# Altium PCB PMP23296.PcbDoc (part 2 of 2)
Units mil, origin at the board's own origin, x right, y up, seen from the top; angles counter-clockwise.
Board outline 4000 x 1600 mil, 2 copper layers (Top Layer, Bottom Layer), stack 62 mil thick; 43 components, 23 nets, 108 pads, 16 vias.
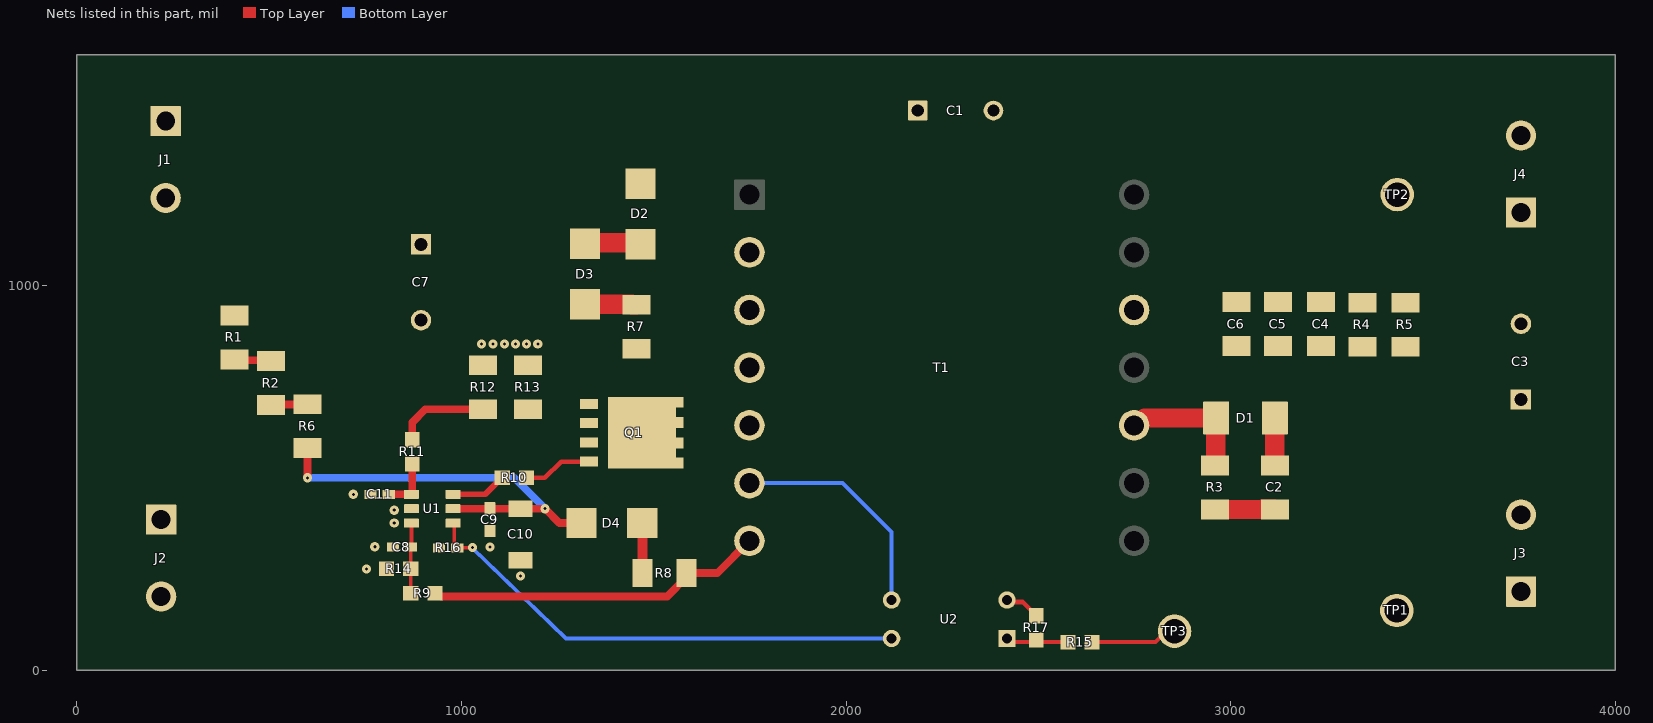
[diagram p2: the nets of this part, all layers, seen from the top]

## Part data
C1: library part CMP-0095357-1, "Cap Ceramic Single Suppression X1/Y2 0.0022uF 250VAC E 20% (8 X 5mm) Radial Disc 5mm 125C Ammo", Digikey Part Number=490-9555-1-ND, Manufacturer=Murata, Mouser Part Number=81-DE2E3KY222MN2AM1F, Operating Temperature Range="-40°C to +125°C", TempCo=+20/-55%, Temperature Characteristic=E, Tolerance_%=20%, ValueDisplayed=2200pF, Voltage Ac Rating X=250V
C2: library part CMP-0008884-2, "CAP, CERM, 100 pF, 630 V, +/- 5%, C0G/NP0, 1206", Cap_Case=1206, Manufacturer=MuRata, Supplier Part Number 1=490-5273-1-ND, TempCo=C0G/NP0, Tolerance_%=5%, Value1=Unknown, Value2=630V, ValueDisplayed=100pF
C3: library part CMP-0010235-2, "CAP, AL, 22 uF, 200 V, +/- 20%, TH", Cap_Case=10x20mm, Manufacturer=Nichicon, Supplier Part Number 1=493-4765-1-ND, Tolerance_%=20%, Value1=Unknown, Value2=200V, ValueDisplayed=22uF
C4 C5 C6: library part CMP-0008585-2, "CAP, CERM, 0.1 uF, 200 V, +/- 10%, X7R, 1206", Cap_Case=1206, Manufacturer=Kemet, Supplier Part Number 1=399-8139-1-ND, TempCo=X7R, Tolerance_%=10%, Value1=Unknown, Value2=200V, ValueDisplayed=0.1uF
C7: library part CMP-0064890-1, "CAP, AL, 22 uF, 200 V, +/- 20%, TH", Cap_Case=10x20mm, Manufacturer=Nichicon, Supplier Part Number 1=493-11959-1-ND, Tolerance_%=20%, Value1=Unknown, Value2=200V, ValueDisplayed=22uF
C8 C11: library part CMP-0064914-2, "CAP, CERM, 10 pF, 10 V,+/- 2.5%, C0G/NP0, 0402", Cap_Case=0402, Manufacturer=Kemet, Supplier Part Number 1=399-8939-1-ND, TempCo=C0G/NP0, Tolerance_%=2.5%, Value1=Unknown, Value2=10V, ValueDisplayed=10pF
C9: library part CMP-0094511-1, "0.1 µF ±5% 50V Ceramic Capacitor X7R 0603 (1608 Metric)", Digikey Part Number=478-7426-1-ND, Manufacturer="KYOCERA AVX", Mouser Part Number=581-06035C104J4Z2A, Operating Temperature Range=to, TempCo=15%, Temperature Characteristic=X7R, Tolerance_%=5%, ValueDisplayed=0.1uF
C10: library part CMP-0008660-2, "CAP, CERM, 2.2 uF, 50 V, +/- 10%, X5R, 1206", Cap_Case=1206_180, Manufacturer=TDK, Supplier Part Number 1=445-14690-1-ND, TempCo=X5R, Tolerance_%=10%, Value1="0.005887 ohm", Value2=50V, ValueDisplayed=2.2uF
D1: library part CMP-0096282-1, "Diode Standard 600 V 2A Surface Mount DO-214AA (SMB)", Digikey Part Number=MURS260-E3/5BTGICT-ND, Forward Current=2A, Manufacturer=Vishay, Max Surge Forward Current=35A, Mouser Part Number=625-MURS260-E3/5BT, Operating Temperature Range="-65°C to +175°C", Peak Reverse Current=5uA
D2: library part CMP-0084980-1, "Diode, TVS, Uni, 120 V, 193 Vc, 400 W, 2.1 A, SMA", Manufacturer=Littelfuse, Value1=193V
D3: library part CMP-0076882-2, "Diode, Ultrafast, 1000 V, 1 A, SMA", Manufacturer="Diodes Inc.", Value1=1A, Value2=1.7V
D4: library part CMP-0081057-2, "Diode, Schottky, 100 V, 4 A, AEC-Q101, SMA", Manufacturer="ON Semiconductor", Value1=4A, Value2=0.68V
J1 J2 J3 J4: library part CMP-0074910-1, "Terminal Block, 5.08 mm, 2x1, Brass, TH", Color=Blue, Current_A=15A, Manufacturer="On-Shore Technology", Supplier Part Number 1=ED1609-ND, Voltage_V=300V
Q1: library part CMP-0000907-1, "MOSFET, N-CH, 300 V, 16 A, PG-TDSON-8", Alternate Manufacturer=None, Manufacturer="Infineon Technologies"
R1 R2 R6: library part CMP-0018313-2, "RES, 470 k, 1%, 0.25 W, 1206", Manufacturer="Yageo America", Power_W=250mW, Supplier Part Number 1=311-470KFRCT-ND, TempCo="100 ppm/C", Tolerance_%=1%, Value2=0.25W, Value_Code=470k
R3: library part CMP-0018748-3, "RES, 0, 5%, 0.25 W, AEC-Q200 Grade 0, 1206", Manufacturer=Panasonic, Power_W=250mW, Supplier Part Number 1=P0.0ECT-ND, TempCo="600 ppm/C", Tolerance_%=5%, Value2=0.25W, Value_Code=0000, ValueDisplayed=0
R4 R5: library part CMP-0017836-2, "RES, 100 k, 1%, 0.25 W, 1206", Manufacturer="Yageo America", Power_W=250mW, Supplier Part Number 1=311-100KFRCT-ND, TempCo="100 ppm/C", Tolerance_%=1%, Value2=0.25W, Value_Code=100k
R7: library part CMP-0018594-3, "RES, 15, 5%, 0.25 W, AEC-Q200 Grade 0, 1206", Manufacturer=Vishay-Dale, Power_W=250mW, Supplier Part Number 1=541-15ECT-ND, TempCo="200 ppm/C", Tolerance_%=5%, Value2=0.25W, Value_Code=15R0, ValueDisplayed=15
R8: library part CMP-0018350-2, "RES, 4.70, 1%, 0.25 W, 1206", Manufacturer="Yageo America", Power_W=250mW, Supplier Part Number 1=311-4.70FRCT-ND, TempCo="200 ppm/C", Tolerance_%=1%, Value2=0.25W, Value_Code=4R70, ValueDisplayed=4.70
R9: library part CMP-0024509-1, "RES, 87.6 k, 0.1%, 0.1 W, 0603", Manufacturer="Yageo America", Power_W=100mW, TempCo="25 ppm/C", Tolerance_%=0.1%, Value2=0.1W, Value_Code=87k6, ValueDisplayed=87.6k
R10: library part CMP-0025874-2, "RES, 0, 5%, 0.1 W, 0603", Manufacturer=Panasonic, Power_W=100mW, Supplier Part Number 1=P0.0GCT-ND, TempCo="600 ppm/C", Tolerance_%=5%, Value2=0.1W, Value_Code=0000, ValueDisplayed=0
R11: library part CMP-0022118-2, "RES, 1.24 k, 1%, 0.1 W, 0603", Manufacturer=Vishay-Dale, Power_W=100mW, Supplier Part Number 1=541-1.24KHCT-ND, TempCo="100 ppm/C", Tolerance_%=1%, Value2=0.1W, Value_Code=1k24, ValueDisplayed=1.24k
R12 R13: library part CMP-0017791-3, "RES, 0.47, 1%, 0.25 W, AEC-Q200 Grade 0, 1206", Manufacturer=Panasonic, Power_W=250mW, Supplier Part Number 1=P.47RCT-ND, TempCo="250 ppm/C", Tolerance_%=1%, Value2=0.25W, Value_Code=R470, ValueDisplayed=0.47
R14: library part CMP-0022261-1, "RES, 28.7 k, 1%, 0.1 W, 0603", Manufacturer=Vishay-Dale, Power_W=100mW, Supplier Part Number 1=541-28.7KHCT-ND, TempCo="100 ppm/C", Tolerance_%=1%, Value2=0.1W, Value_Code=28k7, ValueDisplayed=28.7k
R15 R17: library part CMP-0080488-1, "RES, 10.0 k, 1%, 0.1 W, 0603", Manufacturer="TT Electronics/IRC", Power_W=100mW, TempCo="100 ppm/C", Tolerance_%=1%, Value2=0.1W, Value_Code=10k0, ValueDisplayed=10.0k
R16: library part CMP-0026721-1, "RES, 100 k, 1%, 0.0625 W, 0402", Manufacturer="Yageo America", Power_W=62.5mW, Supplier Part Number 1=311-100KLRCT-ND, TempCo="100 ppm/C", Tolerance_%=1%, Value2=0.0625W, Value_Code=100k
T1: library part CMP-0096302-1, "TRANSFORMER", Frequency_Fixed=25-85kHz, Manufacturer="Wurth Electronics", Operating Temperature Range="-40°C to +125°C", Voltage_Isolation_Vrms=2.85kV
TP1: library part CMP-0055147-2, "Test Point, Multipurpose, Red, TH", Color=Red, Manufacturer="Keystone Electronics", Supplier Part Number 1=36-5010-ND
TP2: library part CMP-0055148-2, "Test Point, Multipurpose, Black, TH", Color=Black, Manufacturer="Keystone Electronics", Supplier Part Number 1=36-5011-ND
TP3: library part CMP-0055150-2, "Test Point, Multipurpose, Orange, TH", Color=Orange, Manufacturer="Keystone Electronics", Supplier Part Number 1=36-5013-ND
U1: library part CMP-0074087-1, "Off-Line Constant-Voltage Constant-Current Flyback Controller With Primary-Side Regulation (PSR), DBV0006A (SOT-23-6)", Alternate Manufacturer="Texas Instruments", Alternate PartNumber=UCC28704DBVT-1
U2: library part CMP-0083653-1, "Optocoupler, 5.3 kV, 100-200% CTR, SMT", Manufacturer=Vishay-Semiconductor, Supplier Part Number 1=VO618A-3-ND, Voltage_Isolation_Vrms=5.3kV

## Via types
v1: diameter 24, hole 8, Top Layer to Bottom Layer, tented both sides, 16 vias

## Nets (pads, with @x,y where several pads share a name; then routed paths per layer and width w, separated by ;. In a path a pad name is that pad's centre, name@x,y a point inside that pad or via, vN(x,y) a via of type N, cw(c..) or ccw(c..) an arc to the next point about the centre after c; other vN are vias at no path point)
BGND: C1.1 C7.2 C8.2 C9.1 C10.2 C11.2 J2.1 J2.2 R12.1 R13.1 R14.1 R16.1 T1.6 U1.5 U2.3 | length 599
  Bottom Layer w10: T1.6@1749.01,486.35 1991.22,486.35 2118.7,358.87 U2.3@2118.7,182.34
  other v1: 1153.72,245 752.95,263.25 1074.33,320 775,320.92 825.38,382.37 825.38,415.93 719.04,457.17 1052.35,847.98 1081.88,847.98 1112.22,847.98 1140.85,847.98 1169.16,847.98 1198.84,847.98
NetC2_1: C2.1 C3.1 C4.1 C5.1 C6.1 D1.1 J3.1 J3.2 R4.2 R5.2 TP1.1 | length 123.5
  Top Layer w50: C2.1@3115.03,532.09 D1.1@3115.03,655.56
NetC2_2: C2.2 R3.2 | length 174.9
  Top Layer w50: R3.2@2973.78,417.91 C2.2@3115.03,417.91 3114.44,418.5 C2.2@3081.65,418.5
NetC7_1: C7.1 D2.2 J1.1 J1.2 R1.2 T1.2
NetC8_1: C8.1 R9.1 R14.2 U1.6 | length 206.3
  Top Layer w10: R9.1@857.51,210.81 R9.1@868.32,200 868.32,263.04 R14.2@868.53,263.25 868.53,319.37 C8.1@869.16,320 870.08,320.92 U1.6@870.08,382.37 U1.6@862.2,382.37
NetC11_1: C11.1 R11.1 U1.4 | length 138.9
  Top Layer w20: C11.1@811.02,457.17 U1.4@870.08,457.17 870.23,457.17 872.04,458.98 R11.1@872.04,536.12
NetD1_2: D1.2 R3.1 T1.10 | length 355.7
  Top Layer w50: T1.10@2749.01,636.35 2757,636.35 2776.21,655.56 2953.72,655.56 2960,649.27 D1.2@2960,640.05 ; R3.1@2960,532.09 2960.65,532.09 2961.24,532.68 2961.24,654.31 D1.2@2962.49,655.56
NetD2_1: D2.1 D3.1 | length 147.3
  Top Layer w50: D3.1@1321.48,1115.32 1325.39,1111.41 1461.64,1111.41 D2.1@1465.55,1107.5
NetD3_2: D3.2 R7.2 | length 134.2
  Top Layer w50: D3.2@1321.48,951.26 1442.68,951.26 1443.61,950.32 1454.44,950.32 R7.2@1455.03,949.73
NetD4_2: D4.2 R8.1 | length 130.4
  Top Layer w25: D4.2@1469.93,382.37 1470.97,381.33 R8.1@1470.97,252.42
NetQ1_1: Q1.1 Q1.2 Q1.3 R11.2 R12.2 R13.2 | length 243.4
  Top Layer w20: R11.2@872.04,599.11 872.04,643.87 906.49,678.32 R12.2@1056.41,678.32
NetQ1_4: Q1.4 R10.2 | length 180
  Top Layer w12: R10.2@1169.16,500.13 1217.19,500.13 1259.35,542.29 Q1.4@1331.69,542.29
NetQ1_5: Q1.5 Q1.6 Q1.7 Q1.8 Q1.9 R7.1 T1.5 | length 47.4
  Top Layer w50: Q1.9@1455.03,631.75 Q1.9@1469.49,617.29 Q1.9@1488.54,636.35
NetR1_1: R1.1 R2.2 | length 101.8
  Top Layer w10: R2.2@505,803.61 R2.2@508.56,807.17
  Top Layer w20: R1.1@410,807.91 412.15,805.76 502.85,805.76 R2.2@505,803.61
NetR2_1: R2.1 R6.2 | length 95.9
  Top Layer w20: R2.1@505,689.44 506.13,690.57 598.87,690.57 R6.2@600,691.7
NetR8_2: R8.2 R9.2 T1.7 | length 867.3
  Top Layer w20: R9.2@948.1,191.47 1535.01,191.47 1585.14,241.59 R8.2@1585.14,252.42 1665.09,252.42 T1.7@1749.01,336.35
NetR10_1: R10.1 U1.3 | length 145.6
  Top Layer w10: R10.1@1105.18,500.13 R10.1@1106.16,500.13
  Top Layer w15: U1.3@978.35,457.17 1062.23,457.17 R10.1@1105.18,500.13
NetR15_1: R15.1 R17.2 U2.1 | length 162
  Top Layer w10: U2.1@2418.7,82.34 2428.29,72.75 R15.1@2576.77,72.75
NetT1_3: T1.3 T1.4
PGND: C1.2 C3.2 C4.2 C5.2 C6.2 J4.1 J4.2 R4.1 R5.1 R17.1 T1.12 TP2.1 U2.2 | length 93.8
  Top Layer w12: U2.2@2418.7,182.34 2423.88,177.16 2459.34,177.16 2481.31,155.18 2482.3,155.18 2495,142.48 R17.1@2495,141.5
Shutdown_PM: R15.2 TP3.1 | length 226.4
  Top Layer w10: R15.2@2639.76,72.75 2804.95,72.75 2833.49,101.3 TP3.1@2854.33,101.3
SU: R16.2 U1.1 U2.4 | length 1295.8
  Top Layer w10: U1.1@978.35,382.37 981.3,379.42 981.3,324.59 988.11,317.78 R16.2@989.38,317.78 990.02,318.42 1028.43,318.42 v1(1029.07,319.06)
  Bottom Layer w10: v1@1028.03,317.78 1272.08,82.34 U2.4@2118.7,82.34
VDD: C9.2 C10.1 D4.1 R6.1 U1.2 | length 1109
  Top Layer w10: R6.1@600,577.53 R6.1@605.67,571.86 ; D4.1@1312.45,382.37 D4.1@1324.39,370.43
  Top Layer w20: v1(600,500.13) R6.1@600,577.53 ; U1.2@978.35,419.77 1073.11,419.77 C9.2@1074.33,420.99 ; C9.2@1070.3,415.93 1074.14,419.77 C10.1@1153.72,419.77 v1(1217.71,419.77) 1255.11,382.37 D4.1@1312.45,382.37
  Bottom Layer w20: v1(600,500.13) 1137.36,500.13 v1(1217.71,419.77)
pads on no net: T1.1 T1.8 T1.9 T1.11 T1.13 T1.14

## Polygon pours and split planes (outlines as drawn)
NetQ1_5 on Top Layer "TOP_LAYER_NETQ1_5_P021" (solid, remove dead copper, pour order 21): 1371.82,512.96 1373.94,510.84 1602.08,510.84 1665.66,574.42 1815.94,574.42 1815.94,688.75 1656.05,688.75 1590.56,754.24 1531.1,754.24 1501.29,784.05 1501.29,869.48 1408.77,869.48 1407.39,868.1 1407.39,782.1 1371.82,746.53
NetC2_1 on Top Layer "TOP_LAYER_NETC2_1_P024" (solid, remove dead copper, pour order 24): 2945.92,875.09 2945.92,746.43 2949.49,750 3065,750 3065,605 3175,605 3175,0 4000,0 4000,875
BGND on Top Layer "TOP_LAYER_BGND_P022" (solid, remove dead copper, pour order 22): 20.85,1010 20.85,85 645,85 790,230 1815.94,230 1815.94,1001.44 1807.39,1010
NetQ1_1 on Top Layer "TOP_LAYER_NETQ1_1_P020" (solid, remove dead copper, pour order 20): 1371.36,735.4 1370.91,734.95 1370.91,572.43 1050.49,572.43 988.31,634.62 990.15,636.46 990.15,735.4
PGND on Top Layer "TOP_LAYER_PGND_P014" (solid, pour order 14): 2680,875 4000,875 4000,1574.51 2680,1574.51
NetT1_3 on Top Layer "TOP_LAYER_NETT1_3_P000" (solid, pour order 0): 1677.3,735.4 1815.94,735.4 1815.94,982.77 1677.3,982.77
NetC7_1 on Top Layer "TOP_LAYER_NETC7_1_P012" (solid, pour order 12): 24.61,1563.91 24.61,895 527.71,895 576.16,943.45 1231.16,943.45 1231.16,1186.24 1240.05,1195.13 1542.32,1195.13 1542.32,1040.81 1581.69,1001.44 1811.67,1001.44 1811.67,1563.91
BGND on Bottom Layer "BOTTOM_LAYER_BGND_P023" (solid, remove dead copper, pour order 23): 25.49,263.25 25.49,85 700.54,85 878.79,263.25
PGND on Bottom Layer "BOTTOM_LAYER_PGND_P013" (solid, pour order 13): 2335,1600 2335,0 4000,0 4000,1600
BGND on Bottom Layer "BOTTOM_LAYER_BGND_P005" (solid, pour order 5): 0,1600 0,230 2215,230 2215,1594.49 5.51,1594.49
no net on M2 Board Dimensions (solid): 2221.46,1600 2224.41,1597.05 2224.41,0

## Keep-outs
Keep-Out Layer:
  text ".Layer_Name" at 577,-858.49 h60

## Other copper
Top Layer:
  text ".Layer_Name" at 577,-858.49 h60
Bottom Layer:
  pour cut-out: 845.54,394.71 903.66,394.71 903.66,228.54 845.54,228.54
  text ".Layer_Name" at 577,-858.49 h60

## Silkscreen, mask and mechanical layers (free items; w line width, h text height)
Top Overlay:
  lines w10: 990.76,223.88 990.76,290.51
  text "Vin" at 521.5,1316.32 h60 r90
  text "B_GND" at 511.5,210.26 h60 r90
  text ".Layer_Name" at 577,-858.49 h60
Bottom Overlay:
  text ".Layer_Name" at 577,-858.49 h60
Top Paste:
  text ".Layer_Name" at 577,-858.49 h60
Bottom Paste:
  text ".Layer_Name" at 577,-858.49 h60
Top Solder:
  text ".Layer_Name" at 577,-858.49 h60
  text ".Layer_Name" at 577,-858.49 h60
Bottom Solder:
  text ".Layer_Name" at 577,-858.49 h60
Drill Guide:
  text ".Layer_Name" at 577,-858.49 h60
M1 Board Outline:
  the board outline again, w10
  text ".Layer_Name" at 577,-858.49 h60
M2 Board Dimensions:
  rectangle: 0,-275 125,-150
  rectangle: 125,-400 500,-275
  lines w7: 0,-275 1000,-275 ; 125,-400 125,-150 ; 250,-400 250,-150 ; 500,-400 500,-150 ; 750,-400 750,-150 ; 0,-400 1000,-400 1000,-150 0,-150 0,-400
  text ".Layer_Name" at 577,-858.49 h60
M3 3D STEP Top:
  text ".Layer_Name" at 577,-858.49 h60
M4 3D STEP Bottom:
  text ".Layer_Name" at 577,-858.49 h60
M5 Assembly Top:
  lines w10: -292,-930.17 6308,-930.17 ; -292,-726.83 6310,-726.83 ; -292,-523.5 -292,-1133.5 3713,-1133.5 6310,-1133.5 6310,-523.5 -291.5,-523.5 -291.5,-1133.5 1284,-1133.5 ; 2173,-1133.5 2173,-523.5 ; 3440,-726.83 3440,-523.5 ; 4280,-726.83 4280,-523.5 ; 4902,-1140 4902,-937.17
  text "COMPONENTS MARKED 'DNP' SHOULD NOT BE POPULATED." at 1153.5,-318.5 h60
  text "ASSEMBLY VARIANT:" at 1153,-434 h60
  text ".VariantName" at 2189,-434 h60
  text "PCB VIEWED FROM TOP SIDE" at -228.5,-655.67 h60
  text "BOARD #:" at 2248,-655.67 h60
  text ".PRJ_Number" at 2793.5,-655.67 h60
  text "REV:" at 3638,-655.67 h60
  text ".PCB_Rev" at 3929.5,-655.67 h60
  text "SVN REV:" at 4476,-655.67 h60
  text ".VersionControl_RevNumber" at 4982,-655.67 h60
  text "TID #:" at 2248,-859 h60
  text ".TID" at 2793.5,-859 h60
  text "PLOT NAME =" at -228.5,-1064.34 h60
  text ".plot_File_Name" at 577,-1064.34 h60
  text "GENERATED    :" at 2250,-1064.34 h60
  text ".Print_Date" at 3119.5,-1064.34 h60
  text ".Print_Time" at 3848.5,-1064.34 h60
  text "TEXAS INSTRUMENTS" at 5113,-1064.34 h60
M6 Assembly Bottom:
  lines w10: -292.5,-727.33 6309.5,-727.33 ; -290.5,-930.67 6309.5,-930.67 ; 1115.5,-1140.5 1115.5,-937.67 ; 1737.5,-727.33 1737.5,-524 ; 2577.5,-727.33 2577.5,-524 ; 3844.5,-1134 3844.5,-524 ; 4733.5,-1134 6309,-1134 6309,-524 -292.5,-524 -292.5,-1134 2304.5,-1134 6309.5,-1134 6309.5,-524
  text "COMPONENTS MARKED 'DNP' SHOULD NOT BE POPULATED." at 6102,-318 h60
  text ".VariantName" at 5058,-434 h60
  text "ASSEMBLY VARIANT:" at 6097,-434 h60
  text ".VersionControl_RevNumber" at 1035.5,-656.17 h60
  text "SVN REV:" at 1541.5,-656.17 h60
  text ".PCB_Rev" at 2088,-656.17 h60
  text "REV:" at 2379.5,-656.17 h60
  text ".PRJ_Number" at 3224,-656.17 h60
  text "BOARD #:" at 3769.5,-656.17 h60
  text "PCB VIEWED FROM BOTTOM SIDE" at 6246,-656.17 h60
  text ".TID" at 3224,-859.5 h60
  text "TID #:" at 3769.5,-859.5 h60
  text "TEXAS INSTRUMENTS" at 904.5,-1064.84 h60
  text ".Print_Time" at 2169,-1064.84 h60
  text ".Print_Date" at 2898,-1064.84 h60
  text "GENERATED    :" at 3767.5,-1064.84 h60
  text ".plot_File_Name" at 5440.5,-1064.84 h60
  text "PLOT NAME =" at 6246,-1064.84 h60
M9 Title Sheet:
  drawing of 57 lines, arcs and shapes, not listed
  text "1" at 739.84,8036.5 h70
  text "2" at 3235.5,8036.5 h70
  text "3" at 5724.84,8036.5 h70
  text "4" at 8231.51,8036.5 h70
  text "5" at 10730.5,8036.5 h70
  text "6" at 13235.5,8036.5 h70
  text "A" at -416.5,6893.5 h70
  text "A" at 14383.5,6893.5 h70
  text "B" at -416.5,4513.5 h70
  text "B" at 14383.5,4513.5 h70
  text "C" at -416.5,2138.5 h70
  text "C" at 14383.5,2138.5 h70
  text "PROJECT TITLE:" at 11343.5,277.5 h45
  text ".PRJ_Title" at 11393.5,144.17 h70
  text "DESIGNED FOR:" at 11343.5,-23.5 h45
  text ".PRJ_Customer" at 11393.5,-163.5 h70
  text "D" at -416.5,-231.5 h70
  text "D" at 14383.5,-231.5 h70
  text "FILE NAME:" at 11343.5,-323.5 h45
  text ".PCB_File_Name_No_Path" at 11393.5,-443.5 h70
  text "Texas Instruments (TI) and/or its licensors do not warrant the accuracy or completeness of this specification" at 6374,-605.34 h45
  text "ENGINEER:" at 11343.5,-613.5 h45
  text "LAYOUT BY:" at 12848.5,-613.5 h45
  text "or any information contained therein. TI and/or its licensors do not warrant that this design will meet" at 6329.01,-718 h45
  text ".PRJ_Engineer" at 11393.5,-768.49 h70
  text ".PCB_Layout" at 12899,-768.49 h70
  text "the specifications, will be suitable for your application or fit for any particular purpose, or will operate in" at 6329.01,-830.67 h45
  text ".Layer_Name" at 577,-858.49 h60
  text "ALTIUM DESIGNER VERSION:" at 12848.5,-923.5 h45
  text "an implementation. TI and/or its licensors do not warrant that the design is production worthy. You should" at 6329.01,-943.33 h45
  text "completely validate and test your design implementation to confirm the system functionality for your application." at 6374,-1056 h45
  text ".print_Scale" at 11393.5,-1056.83 h70
  text ".Application_BuildNumber" at 12899,-1056.83 h70
  text "1" at 739.84,-1263.5 h70
  text "2" at 3235.5,-1263.5 h70
  text "3" at 5724.84,-1263.5 h70
  text "4" at 8231.51,-1263.5 h70
  text "5" at 10730.5,-1263.5 h70
  text "6" at 13235.5,-1263.5 h70
M10 Fab Notes:
  drawing of 189 lines, arcs and shapes, not listed
  text "DESIGN INFORMATION" at 12382.02,6356.17 h60
  text "MIN. TRACK WIDTH:" at 11737.46,6224.05 h60
  text "8" at 12833.7,6224.05 h60
  text "MIL" at 12988.46,6224.05 h60
  text "7.874" at 12667.32,6102.36 h60
  text "MIN. CLEARANCE:" at 11737.46,6099.92 h60
  text "MIL" at 12988.46,6099.92 h60
  text "MIN. VIA PAD SIZE:" at 11737.46,5975.8 h60
  text "24" at 12803.71,5975.8 h60
  text "MIL" at 12988.46,5975.8 h60
  text "0.05mm (2MIL)" at 12432.46,5845.9 h60
  text "MINIMUM ANNULAR RING" at 11408.23,5837.67 h60
  text "EXTERNAL" at 13140.46,5837.67 h60
  text "PER" at 11608.23,5727.55 h60
  text "IPC-D-275 CLASS 2 LEVEL C" at 11828.23,5727.54 h60
  text "MIL, HOLES" at 13316.46,5627.07 h60
  text "+/-" at 12924,5618.48 h60
  text "+/-" at 13778,5618.48 h60
  text "REGISTRATION TOLERANCES:" at 11408.23,5617.42 h60
  text "METAL" at 12608,5617.42 h60
  text "5" at 13184.2,5617.42 h60
  text "3" at 14017.2,5617.42 h60
  text "MIL" at 14133.46,5617.42 h60
  text "HOLE SIZE TOLERANCE (UNLESS OTHERWISE SPECIFIED):" at 11408.23,5519.1 h60
  text "+/-" at 13778,5516.23 h60
  text "3" at 14017.2,5515.17 h60
  text "MIL" at 14133.46,5515.17 h60
  text "MATERIAL:" at 11333.46,5377.52 h60
  text "FR-4 High Tg" at 12319.9,5249 h60
  text "X" at 12175.46,5241.01 h60
  text "FR-408" at 11754.46,5236.49 h60
  text "OTHER" at 13242.46,5236.49 h60
  text "62 MIL (1.6mm) +/-10%" at 12074.56,5093.46 h60
  text "X" at 11954.46,5091.01 h60
  text "THICKNESS:" at 11408.23,5085.24 h60
  text "OTHER" at 13359.46,5085.24 h60
  text "TOLERANCE:" at 11408.23,4946.92 h60
  text "X" at 12256.46,4946.92 h60
  text "ANSI IPC-6012 TYPE 3 CLASS 2" at 12434.48,4946.92 h60
  text "OTHER +/-" at 12434.46,4802.73 h60
  text "BOW & TWIST:" at 11408.23,4657.54 h60
  text "X" at 12256.46,4657.54 h60
  text "ANSI IPC-6012 TYPE 3 CLASS 2" at 12434.48,4657.54 h60
  text "OTHER +/-" at 12434.46,4510.85 h60
  text "DRILLING:" at 11333.46,4380.23 h60
  text "NC_DRILL FILES" at 13094.46,4275.04 h60
  text "REFERENCE:" at 11408.23,4271.1 h60
  text "X" at 12065.46,4271.01 h60
  text "AS SHOWN" at 12243.46,4271.1 h60
  text "X" at 12966.46,4271.1 h60
  text "OTHER" at 13392.46,4128.85 h60
  text "PTH COPPER THICKNESS:" at 11407.91,4125.32 h60
  text "X" at 12547.14,4125.32 h60
  text "20-30 um" at 12675.14,4125.32 h60
  text "BOARD FINISH:" at 11333.46,3977.73 h60
  text "SILKSCREEN:" at 11488.68,3867.6 h60
  text "X" at 12446.46,3867.6 h60
  text "TOP" at 12563.46,3867.6 h60
  text "X" at 12956.46,3867.6 h60
  text "BOTTOM" at 13074.46,3867.6 h60
  text "SILKSCREEN COLOR:" at 11488.68,3712.41 h60
  text "X" at 12445.46,3712.41 h60
  text "WHITE" at 12563.46,3712.41 h60
  text "OTHER" at 13074.46,3712.41 h60
  text "X" at 12576.46,3568.96 h60
  text "GREEN" at 12694.46,3568.96 h60
  text "OTHER" at 13312.46,3568.96 h60
  text "SOLDER RESIST COLOR:" at 11488.68,3562.1 h60
  text "X" at 12576.46,3414.71 h60
  text "MATTE" at 12694.46,3414.71 h60
  text "SEMI-GLOSS" at 13312,3414.07 h60
  text "IMMERSION GOLD (ENIG)" at 12394.46,3241.94 h60
  text "ENEPIG" at 13732,3234.72 h60
  text "SURFACE FINISH:" at 11333.46,3233.72 h60
  text "X" at 12216.46,3233.72 h60
  text "IMM. TIN/SILVER OR EQUIV" at 11663,3096.4 h60
  text "OTHER" at 13094.46,3092.47 h60
  text "ARRAY/PANEL:" at 11333.46,2937.09 h60
  text "CUT AND TRIM PER M1 BOARD OUTLINE" at 12394.46,2928.87 h60
  text "N.C. ROUTE" at 12394.46,2792.9 h60
  text "X" at 13082.46,2792.9 h60
  text "V. SCORE" at 13260.46,2792.9 h60
  text "CERTIFICATION:" at 11333.46,2663.77 h60
  text "MATERIALS AND WORKMANSHIP FOR ALL PCBS" at 12058.46,2663.77 h60
  text "TO MEET OR EXCEED THE REQUIREMENTS OF:" at 12058.46,2569.71 h60
  text "X" at 11695.97,2441.08 h60
  text "ANSI IPC-A-600F CLASS ->" at 11823.96,2441.08 h60
  text "X" at 13471.97,2441.08 h60
  text "2" at 13581.96,2441.08 h60
  text "1" at 13266.96,2439.58 h60
  text "3" at 13935.96,2439.58 h60
  text "X" at 12507.97,2293.39 h60
  text "RoHS" at 12635.96,2293.39 h60
  text "OTHER" at 13280.36,2293.39 h60
  text "PER ORDER" at 13677.42,2293.39 h60
  text "ALL BOARDS MUST MEET OR EXCEED UL94-V0 REQUIREMENTS." at 11361,2139.57 h60
  text "PCB MUST BEAR THE UL94V-0 UL REGISTERED MATERIAL ID NUMBER" at 11361,2023.5 h60
  text "ADDITIONAL REQUIREMENTS:" at 11333.46,1854.08 h60
  text "MICROSECTION:" at 11408.23,1746.95 h60
  text "YES" at 12313.96,1746.95 h60
  text "REQUIRED" at 13175.46,1602.62 h60
  text "BARE BOARD ELEC. TEST:" at 11408.23,1599.76 h60
  text "NONE" at 12713.96,1599.76 h60
  text "X" at 13057.46,1599.76 h60
  text "PER ORDER" at 13767.46,1599.76 h60
  text "XX MIL VIAS REQUIRE NON-CONDUCTIVE FILL AND PLANARIZE" at 11576.38,1394.82 h59
  text "XX MIL VIAS REQUIRE CONDUCTIVE FILL AND PLANARIZE" at 11584.38,1290.84 h60
  text "OUTER XX MIL TRACES REQUIRE 50 OHM SINGLE-ENDED IMPEDANCE" at 11583.39,1127.46 h58
  text "LAYER 2 & 3 (INNER LAYERS) XX MIL WIDE, XX MIL SPACE / TRACES REQUIRE 100 OHM DIFFERENTIAL IMPEDANCE" at 11575.39,891.74 h60
  text ".Layer_Name" at 577,-858.49 h60
M11 Gerber Information:
  lines w10: -292,-930.17 6308,-930.17 ; -292,-726.83 6310,-726.83 ; -292,-523.5 -292,-1133.5 3713,-1133.5 6310,-1133.5 6310,-523.5 -291.5,-523.5 -291.5,-1133.5 1284,-1133.5 ; 2173,-1133.5 2173,-523.5 ; 3440,-726.83 3440,-523.5 ; 4280,-726.83 4280,-523.5 ; 4902,-1140 4902,-937.17
  text "ALL ARTWORK VIEWED FROM TOP SIDE" at -228.5,-655.67 h60
  text "BOARD #:" at 2248,-655.67 h60
  text ".PRJ_Number" at 2793.5,-655.67 h60
  text "REV:" at 3638,-655.67 h60
  text ".PCB_Rev" at 3929.5,-655.67 h60
  text "SVN REV:" at 4476,-655.67 h60
  text ".VersionControl_RevNumber" at 4982,-655.67 h60
  text "LAYER NAME =" at -228.5,-858.49 h60
  text "TID #:" at 2248,-859 h60
  text ".TID" at 2793.5,-859 h60
  text "PLOT NAME =" at -228.5,-1064.34 h60
  text ".plot_File_Name" at 577,-1064.34 h60
  text "GENERATED    :" at 2250,-1064.34 h60
  text ".Print_Date" at 3119.5,-1064.34 h60
  text ".Print_Time" at 3848.5,-1064.34 h60
  text "TEXAS INSTRUMENTS" at 5113,-1064.34 h60
M12 Stackup:
  drawing of 191 lines, arcs and shapes, not listed
  text "Layer" at 9821.59,7874.94 h60
  text "Name" at 10231.51,7874.94 h60
  text "Material" at 11161.25,7874.94 h60
  text "Thickness" at 12021.02,7874.94 h60
  text "Constant" at 12670.85,7874.94 h60
  text "Board Layer Stack" at 13240.71,7874.94 h60
  text "Top Overlay" at 10231.51,7754.94 h60
  text "Top Solder" at 10231.51,7634.94 h60
  text "Solder Resist" at 11161.25,7634.94 h60
  text "0.40mil" at 12021.02,7634.94 h60
  text "3.5" at 12670.85,7634.94 h60
  text "1" at 9821.59,7514.94 h60
  text "Top Layer" at 10231.51,7514.94 h60
  text "1.40mil" at 12021.02,7514.94 h60
  text "Dielectric1" at 10231.51,7394.94 h60
  text "FR-4 High Tg" at 11161.25,7394.94 h60
  text "59.20mil" at 12021.02,7394.94 h60
  text "4.8" at 12670.85,7394.94 h60
  text "2" at 9821.59,7274.94 h60
  text "Bottom Layer" at 10231.51,7274.94 h60
  text "1.40mil" at 12021.02,7274.94 h60
  text "Bottom Solder" at 10231.51,7154.94 h60
  text "Solder Resist" at 11161.25,7154.94 h60
  text "0.40mil" at 12021.02,7154.94 h60
  text "3.5" at 12670.85,7154.94 h60
  text "Bottom Overlay" at 10231.51,7034.94 h60
  text ".Layer_Name" at 577,-858.49 h60
M13 Component Bodies Top:
  text ".Layer_Name" at 577,-858.49 h60
M14 Component Bodies Bottom:
  text ".Layer_Name" at 577,-858.49 h60
M15 Courtyards Top:
  text ".Layer_Name" at 577,-858.49 h60
M16 Courtyards Bottom:
  text ".Layer_Name" at 577,-858.49 h60
Drill Drawing:
  circle w10: c5363.72,3041.64 r27.63
  lines w10: 5336.09,2530.55 5349.9,2530.55 5363.72,2516.74 5377.53,2530.55 5391.34,2530.55 5377.53,2544.36 5391.34,2558.18 5377.53,2558.18 5363.72,2571.99 5349.9,2558.18 5336.09,2558.18 5349.9,2544.36 5336.09,2530.55 ; 5336.09,2641.06 5391.34,2641.06 5391.34,2696.31 5336.09,2696.31 5336.09,2641.06 ; 5336.09,2820.63 5391.34,2820.63 5363.72,2765.38 5336.09,2820.63 ; 5336.09,2889.7 5363.72,2903.51 5391.34,2889.7 5377.53,2917.32 5391.34,2944.95 5363.72,2931.14 5336.09,2944.95 5349.9,2917.32 5336.09,2889.7 ; 5336.09,3152.15 5349.9,3152.15 5349.9,3138.34 5377.53,3138.34 5377.53,3152.15 5391.34,3152.15 5391.34,3179.78 5377.53,3179.78 5377.53,3193.59 5349.9,3193.59 5349.9,3179.78 5336.09,3179.78 5336.09,3152.15 ; 5336.09,3262.66 5391.34,3262.66 5391.34,3317.91 5336.09,3317.91 5336.09,3262.66 ; 5347.14,3273.71 5380.29,3273.71 5380.29,3306.86 5347.14,3306.86 5347.14,3273.71
  lines w12: 5286,2479.44 8517.49,2479.44 ; 5286,3349.68 8517.49,3349.68 ; 5623.86,2355.12 5623.86,3474 ; 5955.86,2355.12 5955.86,3474 ; 6592.43,2355.12 6592.43,3474 ; 6851.57,2355.12 6851.57,3474 ; 7226.72,2355.12 7226.72,3474 ; 7951.05,2355.12 7951.05,3474 ; 5286,2355.12 8517.49,2355.12 8517.49,3474 5286,3474 5286,2355.12
  text "Symbol" at 5360.59,3386.98 h72
  text "Quantity" at 5661.16,3386.98 h72
  text "Finished Hole Size" at 5993.16,3386.98 h72
  text "Plated" at 6629.72,3386.98 h72
  text "Hole Type" at 6888.86,3386.98 h72
  text "Drill Layer Pair" at 7264.02,3386.98 h72
  text "Hole Tolerance" at 7988.35,3386.98 h72
  text "16" at 5661.16,3262.66 h60
  text "8.00mil (0.203mm)" at 5993.16,3262.66 h60
  text "PTH" at 6629.72,3262.66 h60
  text "Round" at 6888.86,3262.66 h60
  text "Top Layer - Bottom Layer" at 7264.02,3262.66 h60
  text "4" at 5661.16,3138.34 h60
  text "25.59mil (0.650mm)" at 5993.16,3138.34 h60
  text "PTH" at 6629.72,3138.34 h60
  text "Round" at 6888.86,3138.34 h60
  text "Top Layer - Bottom Layer" at 7264.02,3138.34 h60
  text "2" at 5661.16,3014.02 h60
  text "31.50mil (0.800mm)" at 5993.16,3014.02 h60
  text "PTH" at 6629.72,3014.02 h60
  text "Round" at 6888.86,3014.02 h60
  text "Top Layer - Bottom Layer" at 7264.02,3014.02 h60
  text "4" at 5661.16,2889.7 h60
  text "33.47mil (0.850mm)" at 5993.16,2889.7 h60
  text "PTH" at 6629.72,2889.7 h60
  text "Round" at 6888.86,2889.7 h60
  text "Top Layer - Bottom Layer" at 7264.02,2889.7 h60
  text "8" at 5661.16,2765.38 h60
  text "49.21mil (1.250mm)" at 5993.16,2765.38 h60
  text "PTH" at 6629.72,2765.38 h60
  text "Round" at 6888.86,2765.38 h60
  text "Top Layer - Bottom Layer" at 7264.02,2765.38 h60
  text "14" at 5661.16,2641.06 h60
  text "51.97mil (1.320mm)" at 5993.16,2641.06 h60
  text "PTH" at 6629.72,2641.06 h60
  text "Round" at 6888.86,2641.06 h60
  text "Top Layer - Bottom Layer" at 7264.02,2641.06 h60
  text "3" at 5661.16,2516.74 h60
  text "63.00mil (1.600mm)" at 5993.16,2516.74 h60
  text "PTH" at 6629.72,2516.74 h60
  text "Round" at 6888.86,2516.74 h60
  text "Top Layer - Bottom Layer" at 7264.02,2516.74 h60
  text "51 Total" at 5661.16,2392.42 h60
  text ".Layer_Name" at 577,-858.49 h60
M17 Embedded Cavity:
  text ".Layer_Name" at 577,-858.49 h60
M18 Embedded Assembly:
  text ".Layer_Name" at 577,-858.49 h60
M19 Embedded Keepout:
  text ".Layer_Name" at 577,-858.49 h60

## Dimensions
0,-400 to 1000,-400 on M2 Board Dimensions
0,0 to 0,1600 on M2 Board Dimensions
0,0 to 4000,0 on M2 Board Dimensions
